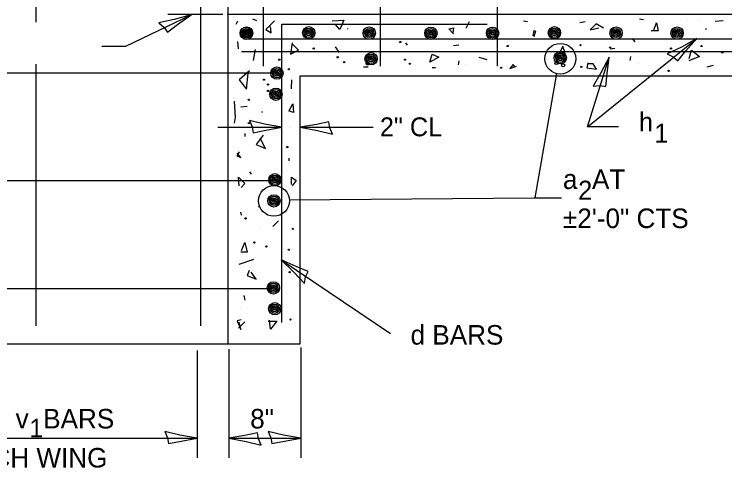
# Model space of a CAD drawing. Extents: x 2133490 to 2172050, y 2138301 to 2145980.
# Drawn here: x 2136576.6 to 2136795.1, y 2145249.3 to 2145388.7 of the extents above; entities that cross this region are included whole.
import ezdxf

# ---------------------------------------------------------------- set-up
doc = ezdxf.new("R2010")
doc.units = 0
for name, color, linetype in [('Level 40', 7, 'Continuous'), ('Level 63', 7, 'Continuous'), ('ROW_PR_Notes', 7, 'Continuous')]:
    doc.layers.add(name, color=color, linetype=linetype)

msp = doc.modelspace()

# ---------------------------------------------------------------- linework, layer by layer
at = {"layer": 'Level 40'}
for centre, radius in [((2136648.06, 2145382.9), 1.89), ((2136667.16, 2145382.98), 1.89), ((2136685.78, 2145382.9), 1.89), ((2136742.71, 2145382.98), 1.89), ((2136761.66, 2145382.9), 1.89), ((2136780.44, 2145382.9), 1.89), ((2136647.97, 2145382.82), 1.89), ((2136646.94, 2145383.16), 0.473), ((2136647.97, 2145382.82), 1.42), ((2136647.03, 2145383.25), 0.473), ((2136648.06, 2145382.9), 1.42), ((2136647.97, 2145382.82), 0.947), ((2136648.06, 2145382.9), 0.947), ((2136647.62, 2145383.16), 0.473), ((2136647.71, 2145383.25), 0.473), ((2136647.97, 2145382.82), 0.473), ((2136648.06, 2145382.9), 0.473), ((2136648.99, 2145382.47), 0.473), ((2136649.08, 2145382.56), 0.473), ((2136666.14, 2145383.32), 0.473), ((2136667.16, 2145382.98), 1.42), ((2136667.16, 2145382.98), 0.947), ((2136666.82, 2145383.32), 0.473), ((2136667.16, 2145382.98), 0.473), ((2136668.19, 2145382.64), 0.473), ((2136684.75, 2145383.24), 0.473), ((2136685.78, 2145382.9), 1.42), ((2136685.78, 2145382.9), 0.947), ((2136685.44, 2145383.24), 0.473), ((2136685.78, 2145382.9), 0.473), ((2136686.81, 2145382.56), 0.473), ((2136704.73, 2145382.82), 1.89), ((2136703.7, 2145383.16), 0.473), ((2136704.73, 2145382.82), 1.42), ((2136704.73, 2145382.82), 0.947), ((2136704.39, 2145383.16), 0.473), ((2136704.73, 2145382.82), 0.473), ((2136705.76, 2145382.47), 0.473), ((2136723.68, 2145382.82), 1.89), ((2136722.65, 2145383.16), 0.473), ((2136723.68, 2145382.82), 1.42), ((2136723.68, 2145382.82), 0.947), ((2136723.33, 2145383.16), 0.473), ((2136723.68, 2145382.82), 0.473), ((2136724.7, 2145382.47), 0.473), ((2136741.68, 2145383.32), 0.473), ((2136742.71, 2145382.98), 1.42), ((2136742.71, 2145382.98), 0.947), ((2136742.37, 2145383.32), 0.473), ((2136742.71, 2145382.98), 0.473), ((2136743.73, 2145382.64), 0.473), ((2136760.63, 2145383.24), 0.473), ((2136761.66, 2145382.9), 1.42), ((2136761.66, 2145382.9), 0.947), ((2136761.31, 2145383.24), 0.473), ((2136761.66, 2145382.9), 0.473), ((2136762.68, 2145382.55), 0.473), ((2136779.41, 2145383.24), 0.473), ((2136780.44, 2145382.9), 1.42), ((2136780.44, 2145382.9), 0.947), ((2136780.1, 2145383.24), 0.473), ((2136780.44, 2145382.9), 0.473), ((2136781.47, 2145382.55), 0.473), ((2136668.69, 2145378.16), 0.189), ((2136695.3, 2145380.13), 0.189), ((2136728.31, 2145378.9), 0.189), ((2136750.73, 2145379.15), 0.189), ((2136759.84, 2145378.41), 0.189), ((2136778.57, 2145378.16), 0.189), ((2136787.93, 2145378.9), 0.189), ((2136686.33, 2145374.99), 1.89), ((2136686.33, 2145374.99), 1.42), ((2136744.52, 2145375.29), 1.89), ((2136743.49, 2145375.63), 0.473), ((2136744.52, 2145375.29), 1.42), ((2136744.52, 2145375.29), 0.947), ((2136744.18, 2145375.63), 0.473), ((2136794.33, 2145376.93), 0.189), ((2136658.1, 2145374.71), 0.189), ((2136676.08, 2145375.45), 0.189), ((2136678.05, 2145373.97), 0.189), ((2136685.31, 2145375.33), 0.473), ((2136685.31, 2145373.52), 0.473), ((2136686.33, 2145374.99), 0.947), ((2136685.99, 2145375.33), 0.473), ((2136686.33, 2145374.99), 0.473), ((2136687.36, 2145374.65), 0.473), ((2136696.77, 2145374.71), 0.189), ((2136743.34, 2145373.67), 0.473), ((2136744.52, 2145375.29), 0.473), ((2136745.54, 2145374.95), 0.473), ((2136657.4, 2145370.57), 1.89), ((2136657.4, 2145370.57), 1.42), ((2136661.05, 2145371.76), 0.189), ((2136698.25, 2145373.48), 0.189), ((2136726.34, 2145372.25), 0.189), ((2136745.39, 2145372.99), 0.473), ((2136750.97, 2145372.5), 0.189), ((2136656.37, 2145370.91), 0.473), ((2136657.4, 2145370.57), 0.947), ((2136657.06, 2145370.91), 0.473), ((2136657.4, 2145370.57), 0.473), ((2136658.42, 2145370.23), 0.473), ((2136777.83, 2145371.26), 0.189), ((2136653.42, 2145368.55), 0.189), ((2136654.65, 2145367.08), 0.189), ((2136654.65, 2145365.11), 0.189), ((2136657.08, 2145364.09), 1.89), ((2136657.08, 2145364.09), 1.42), ((2136656.06, 2145364.43), 0.473), ((2136657.08, 2145364.09), 0.947), ((2136656.74, 2145364.43), 0.473), ((2136657.08, 2145364.09), 0.473), ((2136658.11, 2145363.75), 0.473), ((2136648.73, 2145362.39), 0.189), ((2136648.73, 2145355.25), 0.189), ((2136660.56, 2145347.86), 0.189), ((2136656.74, 2145337.8), 1.89), ((2136656.74, 2145337.8), 1.42), ((2136655.71, 2145338.14), 0.473), ((2136656.74, 2145337.8), 0.947), ((2136656.39, 2145338.14), 0.473), ((2136656.74, 2145337.8), 0.473), ((2136657.76, 2145337.46), 0.473), ((2136656.47, 2145331.33), 1.89), ((2136656.47, 2145331.33), 1.42), ((2136655.44, 2145331.67), 0.473), ((2136656.47, 2145331.33), 0.947), ((2136656.12, 2145331.67), 0.473), ((2136656.47, 2145331.33), 0.473), ((2136657.49, 2145330.99), 0.473), ((2136647.75, 2145325.93), 0.189), ((2136662.28, 2145322.73), 0.189), ((2136650.46, 2145318.54), 0.189), ((2136654.15, 2145317.31), 0.189), ((2136661.05, 2145316.33), 0.189), ((2136661.3, 2145309.43), 0.189), ((2136656.29, 2145304.59), 1.89), ((2136655.26, 2145304.93), 0.473), ((2136656.29, 2145304.59), 1.42), ((2136656.29, 2145304.59), 0.947), ((2136655.94, 2145304.93), 0.473), ((2136656.29, 2145304.59), 0.473), ((2136657.31, 2145304.25), 0.473), ((2136656.71, 2145298.19), 1.89), ((2136656.71, 2145298.19), 1.42), ((2136655.69, 2145298.53), 0.473), ((2136656.71, 2145298.19), 0.947), ((2136656.37, 2145298.53), 0.473), ((2136656.71, 2145298.19), 0.473), ((2136657.74, 2145297.85), 0.473), ((2136661.55, 2145294.89), 0.189)]:
    msp.add_circle(centre, radius, dxfattribs=at)
at = {"layer": 'Level 63'}
for p, q in [((2136743.32, 2145370.42), (2136736.71, 2145332.21)), ((2136639.24, 2145353.92), (2136658.93, 2145353.92)), ((2136664.52, 2145353.92), (2136687.01, 2145353.92)), ((2136661.25, 2145331.61), (2136736.53, 2145332.24)), ((2136736.53, 2145332.24), (2136744.91, 2145332.24)), ((2136632.9, 2145285.36), (2136632.9, 2145252.4)), ((2136642.55, 2145285.81), (2136642.55, 2145252.4)), ((2136664.71, 2145286.26), (2136664.71, 2145252.4)), ((2136532.81, 2145258.4), (2136632.9, 2145258.4)), ((2136642.55, 2145258.4), (2136664.71, 2145258.4))]:
    msp.add_line(p, q, dxfattribs=at)
for points in [[(2136621.06, 2145386.04), (2136622.63, 2145384.67), (2136623.72, 2145383.15), (2136626.84, 2145385.56), (2136630.96, 2145388.53), (2136625.74, 2145387.07)], [(2136777.41, 2145376.55), (2136779.26, 2145375.56), (2136780.66, 2145374.33), (2136783.16, 2145377.39), (2136786.51, 2145381.2), (2136781.75, 2145378.6)], [(2136754.58, 2145366.54), (2136756.65, 2145366.75), (2136758.51, 2145366.51), (2136758.88, 2145370.44), (2136759.52, 2145375.47), (2136757.03, 2145370.66)], [(2136648.93, 2145356.01), (2136649.74, 2145354.09), (2136650.06, 2145352.24), (2136653.93, 2145353.05), (2136658.93, 2145353.92), (2136653.59, 2145354.89)], [(2136674.52, 2145351.82), (2136673.7, 2145353.75), (2136673.39, 2145355.59), (2136669.52, 2145354.78), (2136664.52, 2145353.92), (2136669.85, 2145352.95)], [(2136665.81, 2145305.9), (2136666.21, 2145307.95), (2136666.98, 2145309.66), (2136663.32, 2145311.15), (2136658.68, 2145313.22), (2136662.57, 2145309.44)], [(2136622.9, 2145260.5), (2136623.72, 2145258.57), (2136624.03, 2145256.73), (2136627.9, 2145257.54), (2136632.9, 2145258.4), (2136627.57, 2145259.37)], [(2136654.71, 2145260.5), (2136655.52, 2145258.57), (2136655.84, 2145256.73), (2136659.71, 2145257.54), (2136664.71, 2145258.4), (2136659.37, 2145259.37)], [(2136652.55, 2145256.31), (2136651.73, 2145258.23), (2136651.42, 2145260.08), (2136647.55, 2145259.27), (2136642.55, 2145258.4), (2136647.88, 2145257.43)]]:
    msp.add_lwpolyline(points, close=True, dxfattribs=at)
for centre in [(2136744.52, 2145374.99), (2136656.47, 2145331.33)]:
    msp.add_circle(centre, 4.73, dxfattribs=at)
at = {"layer": 'ROW_PR_Notes'}
for p, q in [((2136642.39, 2145287.36), (2136642.39, 2145540.13)), ((2136633.97, 2145292.92), (2136633.97, 2145521.11)), ((2136653.24, 2145372.69), (2136653.24, 2145515.83)), ((2136689.22, 2145372.69), (2136689.22, 2145515.83)), ((2136583.38, 2145386.19), (2136583.38, 2145505.9)), ((2136725.19, 2145372.69), (2136725.19, 2145455.94)), ((2136623.86, 2145388.66), (2136640.72, 2145388.66)), ((2136642.04, 2145388.66), (2136843.46, 2145388.66)), ((2136651.17, 2145386.64), (2136649.94, 2145387.17)), ((2136770.11, 2145387), (2136768.87, 2145387.17)), ((2136786.94, 2145387.03), (2136786.94, 2145387.03)), ((2136645.28, 2145386.54), (2136644.79, 2145385.55)), ((2136656.63, 2145386.64), (2136653.99, 2145384.01)), ((2136655.57, 2145382.95), (2136655.4, 2145384.88)), ((2136658.85, 2145385.59), (2136722.07, 2145385.59)), ((2136658.93, 2145293.91), (2136658.93, 2145385.59)), ((2136674.4, 2145386.64), (2136677.92, 2145386.82)), ((2136676.69, 2145384.01), (2136675.28, 2145385.59)), ((2136677.92, 2145386.82), (2136676.69, 2145384.01)), ((2136716.48, 2145386.29), (2136715.5, 2145384.32)), ((2136734.47, 2145386.29), (2136733.23, 2145386.54)), ((2136752.2, 2145386.29), (2136750.48, 2145386.04)), ((2136755.5, 2145385.76), (2136753.74, 2145383.83)), ((2136757.79, 2145384.36), (2136755.5, 2145385.76)), ((2136773.14, 2145383.58), (2136774.13, 2145386.04)), ((2136774.13, 2145386.04), (2136774.62, 2145383.58)), ((2136783.48, 2145386.82), (2136783.48, 2145386.82)), ((2136794.56, 2145386.64), (2136792.1, 2145386.47)), ((2136653.99, 2145384.01), (2136655.57, 2145382.95)), ((2136679.04, 2145384.32), (2136679.04, 2145384.07)), ((2136710.29, 2145384.18), (2136711.7, 2145384.53)), ((2136711.7, 2145382.6), (2136710.29, 2145384.18)), ((2136711.7, 2145384.53), (2136711.52, 2145382.95)), ((2136736.15, 2145382.07), (2136736.5, 2145383.65)), ((2136736.85, 2145383.48), (2136736.33, 2145381.72)), ((2136736.5, 2145383.65), (2136736.85, 2145383.48)), ((2136753.74, 2145383.83), (2136756.38, 2145384.53)), ((2136774.62, 2145383.58), (2136772.41, 2145383.58)), ((2136789.4, 2145384.32), (2136789.16, 2145383.83)), ((2136839.15, 2145380.99), (2136647.06, 2145380.99)), ((2136766.59, 2145381.19), (2136767.47, 2145380.14)), ((2136645.55, 2145378.02), (2136645.37, 2145380.31)), ((2136662.04, 2145379.89), (2136661.54, 2145376.44)), ((2136664.01, 2145377.67), (2136662.28, 2145379.39)), ((2136675.34, 2145378.65), (2136676.57, 2145376.93)), ((2136697.51, 2145379.15), (2136697.02, 2145379.89)), ((2136711.7, 2145379.08), (2136713.28, 2145379.25)), ((2136745.3, 2145378.9), (2136744.32, 2145376.68)), ((2136746.04, 2145376.93), (2136745.3, 2145378.65)), ((2136761.32, 2145378.16), (2136759.84, 2145377.91)), ((2136838.54, 2145377.12), (2136646.45, 2145377.12)), ((2136650.65, 2145377.85), (2136650.12, 2145374.5)), ((2136661.54, 2145376.44), (2136664.01, 2145377.67)), ((2136704.41, 2145373.97), (2136705.15, 2145376.44)), ((2136705.15, 2145376.44), (2136707.12, 2145375.45)), ((2136744.32, 2145376.68), (2136746.04, 2145376.93)), ((2136782.01, 2145377.18), (2136782.01, 2145377.18)), ((2136784.18, 2145375.03), (2136784.88, 2145377.67)), ((2136784.88, 2145377.67), (2136787.35, 2145375.73)), ((2136707.12, 2145375.45), (2136704.41, 2145373.97)), ((2136713.28, 2145374.33), (2136713.1, 2145373.1)), ((2136722.08, 2145374.68), (2136719.61, 2145375.38)), ((2136766.06, 2145375.73), (2136765.88, 2145374.5)), ((2136787.35, 2145375.73), (2136784, 2145374.33)), ((2136583.38, 2145292.92), (2136583.38, 2145373.28)), ((2136683.96, 2145372.49), (2136685.44, 2145372.49)), ((2136706.13, 2145372.25), (2136705.15, 2145372.25)), ((2136715.5, 2145373.23), (2136715.5, 2145373.23)), ((2136730.03, 2145373.23), (2136729.04, 2145372)), ((2136729.04, 2145372), (2136731.02, 2145372.74)), ((2136730.53, 2145372.49), (2136730.03, 2145373.23)), ((2136752.94, 2145373.73), (2136752.69, 2145372.25)), ((2136752.69, 2145372.25), (2136755.65, 2145371.76)), ((2136754.67, 2145373.48), (2136753.19, 2145373.48)), ((2136755.65, 2145371.76), (2136754.67, 2145373.48)), ((2136768.46, 2145373.48), (2136768.46, 2145373.48)), ((2136789.65, 2145372.49), (2136791.62, 2145372.99)), ((2136525.01, 2145370.67), (2136656.12, 2145370.67)), ((2136648.98, 2145371.26), (2136645.78, 2145368.55)), ((2136647.99, 2145365.6), (2136648.49, 2145370.52)), ((2136664.52, 2145287.36), (2136664.52, 2145369.72)), ((2136664.52, 2145369.72), (2136816.91, 2145369.72)), ((2136645.78, 2145368.55), (2136647.99, 2145365.6)), ((2136661.91, 2145368.52), (2136661.73, 2145365.71)), ((2136644.31, 2145361.84), (2136644.31, 2145362.01)), ((2136644.66, 2145357.09), (2136644.31, 2145361.84)), ((2136661.03, 2145358.85), (2136662.26, 2145361.13)), ((2136662.26, 2145361.13), (2136662.43, 2145358.49)), ((2136646.27, 2145360.18), (2136648.24, 2145360.42)), ((2136652.67, 2145358.7), (2136652.92, 2145358.7)), ((2136662.43, 2145358.49), (2136661.03, 2145359.02)), ((2136644.31, 2145355.15), (2136644.66, 2145357.09)), ((2136644.66, 2145357.09), (2136644.66, 2145357.09)), ((2136644.31, 2145355.15), (2136644.31, 2145355.15)), ((2136647.5, 2145352.05), (2136647.5, 2145351.06)), ((2136661.54, 2145354.02), (2136661.54, 2145354.02)), ((2136653.17, 2145351.55), (2136650.95, 2145348.6)), ((2136653.9, 2145347.37), (2136652.18, 2145350.57)), ((2136650.95, 2145348.6), (2136653.9, 2145347.37)), ((2136645.72, 2145346.36), (2136645.02, 2145345.12)), ((2136646.25, 2145344.6), (2136645.19, 2145346)), ((2136645.02, 2145345.12), (2136646.25, 2145344.6)), ((2136661.05, 2145344.41), (2136661.05, 2145343.67)), ((2136648.98, 2145340.22), (2136649.47, 2145339.48)), ((2136525.01, 2145337.54), (2136656.12, 2145337.54)), ((2136645.72, 2145335.98), (2136645.55, 2145338.61)), ((2136645.55, 2145338.61), (2136647.48, 2145336.68)), ((2136647.48, 2145336.68), (2136646.42, 2145335.45)), ((2136661.91, 2145336.33), (2136661.91, 2145338.61)), ((2136661.91, 2145338.61), (2136663.31, 2145337.56)), ((2136663.31, 2145337.56), (2136662.08, 2145335.98)), ((2136651.69, 2145329.63), (2136651.69, 2145329.38)), ((2136646.51, 2145326.92), (2136646.27, 2145327.9)), ((2136656.12, 2145323.47), (2136657.85, 2145325.2)), ((2136652.18, 2145322.98), (2136652.18, 2145322.98)), ((2136646.51, 2145316.08), (2136647.5, 2145318.54)), ((2136647.5, 2145318.54), (2136648.24, 2145315.59)), ((2136648.24, 2145315.59), (2136646.27, 2145315.59)), ((2136645.72, 2145311.87), (2136650.29, 2145313.46)), ((2136658.68, 2145313.22), (2136692.3, 2145290.61)), ((2136648.89, 2145309.94), (2136648.18, 2145308.35)), ((2136648.18, 2145308.35), (2136651, 2145307.3)), ((2136651, 2145307.3), (2136649.41, 2145309.41)), ((2136525.01, 2145304.4), (2136656.12, 2145304.4)), ((2136647.66, 2145300.79), (2136647.3, 2145302.2)), ((2136646.27, 2145298.59), (2136646.27, 2145298.59)), ((2136646.42, 2145294.81), (2136645.19, 2145294.45)), ((2136645.19, 2145294.45), (2136646.25, 2145291.82)), ((2136645.53, 2145292.18), (2136647.5, 2145294.15)), ((2136646.25, 2145291.82), (2136645.72, 2145294.1)), ((2136654.65, 2145294.4), (2136657.35, 2145294.4)), ((2136655.39, 2145291.94), (2136655.14, 2145294.65)), ((2136657.35, 2145294.4), (2136655.39, 2145291.94)), ((2136509.85, 2145287.36), (2136664.52, 2145287.36))]:
    msp.add_line(p, q, dxfattribs=at)
for points in [[(2136603.58, 2145378.81), (2136610.97, 2145378.81), (2136630.96, 2145388.53)], [(2136762.39, 2145354.07), (2136752.92, 2145354.07), (2136786.51, 2145381.2)], [(2136762.39, 2145354.07), (2136752.92, 2145354.07), (2136759.52, 2145375.47)]]:
    msp.add_lwpolyline(points, dxfattribs=at)

# ---------------------------------------------------------------- texts
at = {"layer": 'Level 63'}
for s, height, p in [('2" CL', 5.8, (2136689.05, 2145351.17)), ('a  AT', 6, (2136745.34, 2145334.97)), ('2', 5.8, (2136750.02, 2145331.72)), ('±2\'-0" CTS', 6, (2136745.34, 2145322.97)), ('  - #   v  BARS', 6, (2136556.53, 2145261.4)), ('8"', 6, (2136649.16, 2145261.4)), ('1', 5.68, (2136581.27, 2145258.69)), ('EACH WING', 6, (2136558.9, 2145249.4))]:
    msp.add_text(s, height=height, dxfattribs=at).set_placement(p)
at = {"layer": 'ROW_PR_Notes'}
for s, height, p in [('h ', 5.8, (2136768.72, 2145352.68)), ('1', 5.8, (2136773.42, 2145349.23)), ('d BARS', 6, (2136698.48, 2145287.16))]:
    msp.add_text(s, height=height, dxfattribs=at).set_placement(p)

doc.saveas('drawing.dxf')
